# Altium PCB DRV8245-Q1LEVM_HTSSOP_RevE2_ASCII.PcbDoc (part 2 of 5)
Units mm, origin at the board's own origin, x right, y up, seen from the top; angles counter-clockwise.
Board outline 81.9 x 103.6 mm, 4 copper layers (Top Layer, Signal Layer 1, Signal Layer 2, Bottom Layer), stack 1.554 mm thick; 187 components, 116 nets, 590 pads, 1182 vias.
Unrouted connection lines stored in the file: 116.
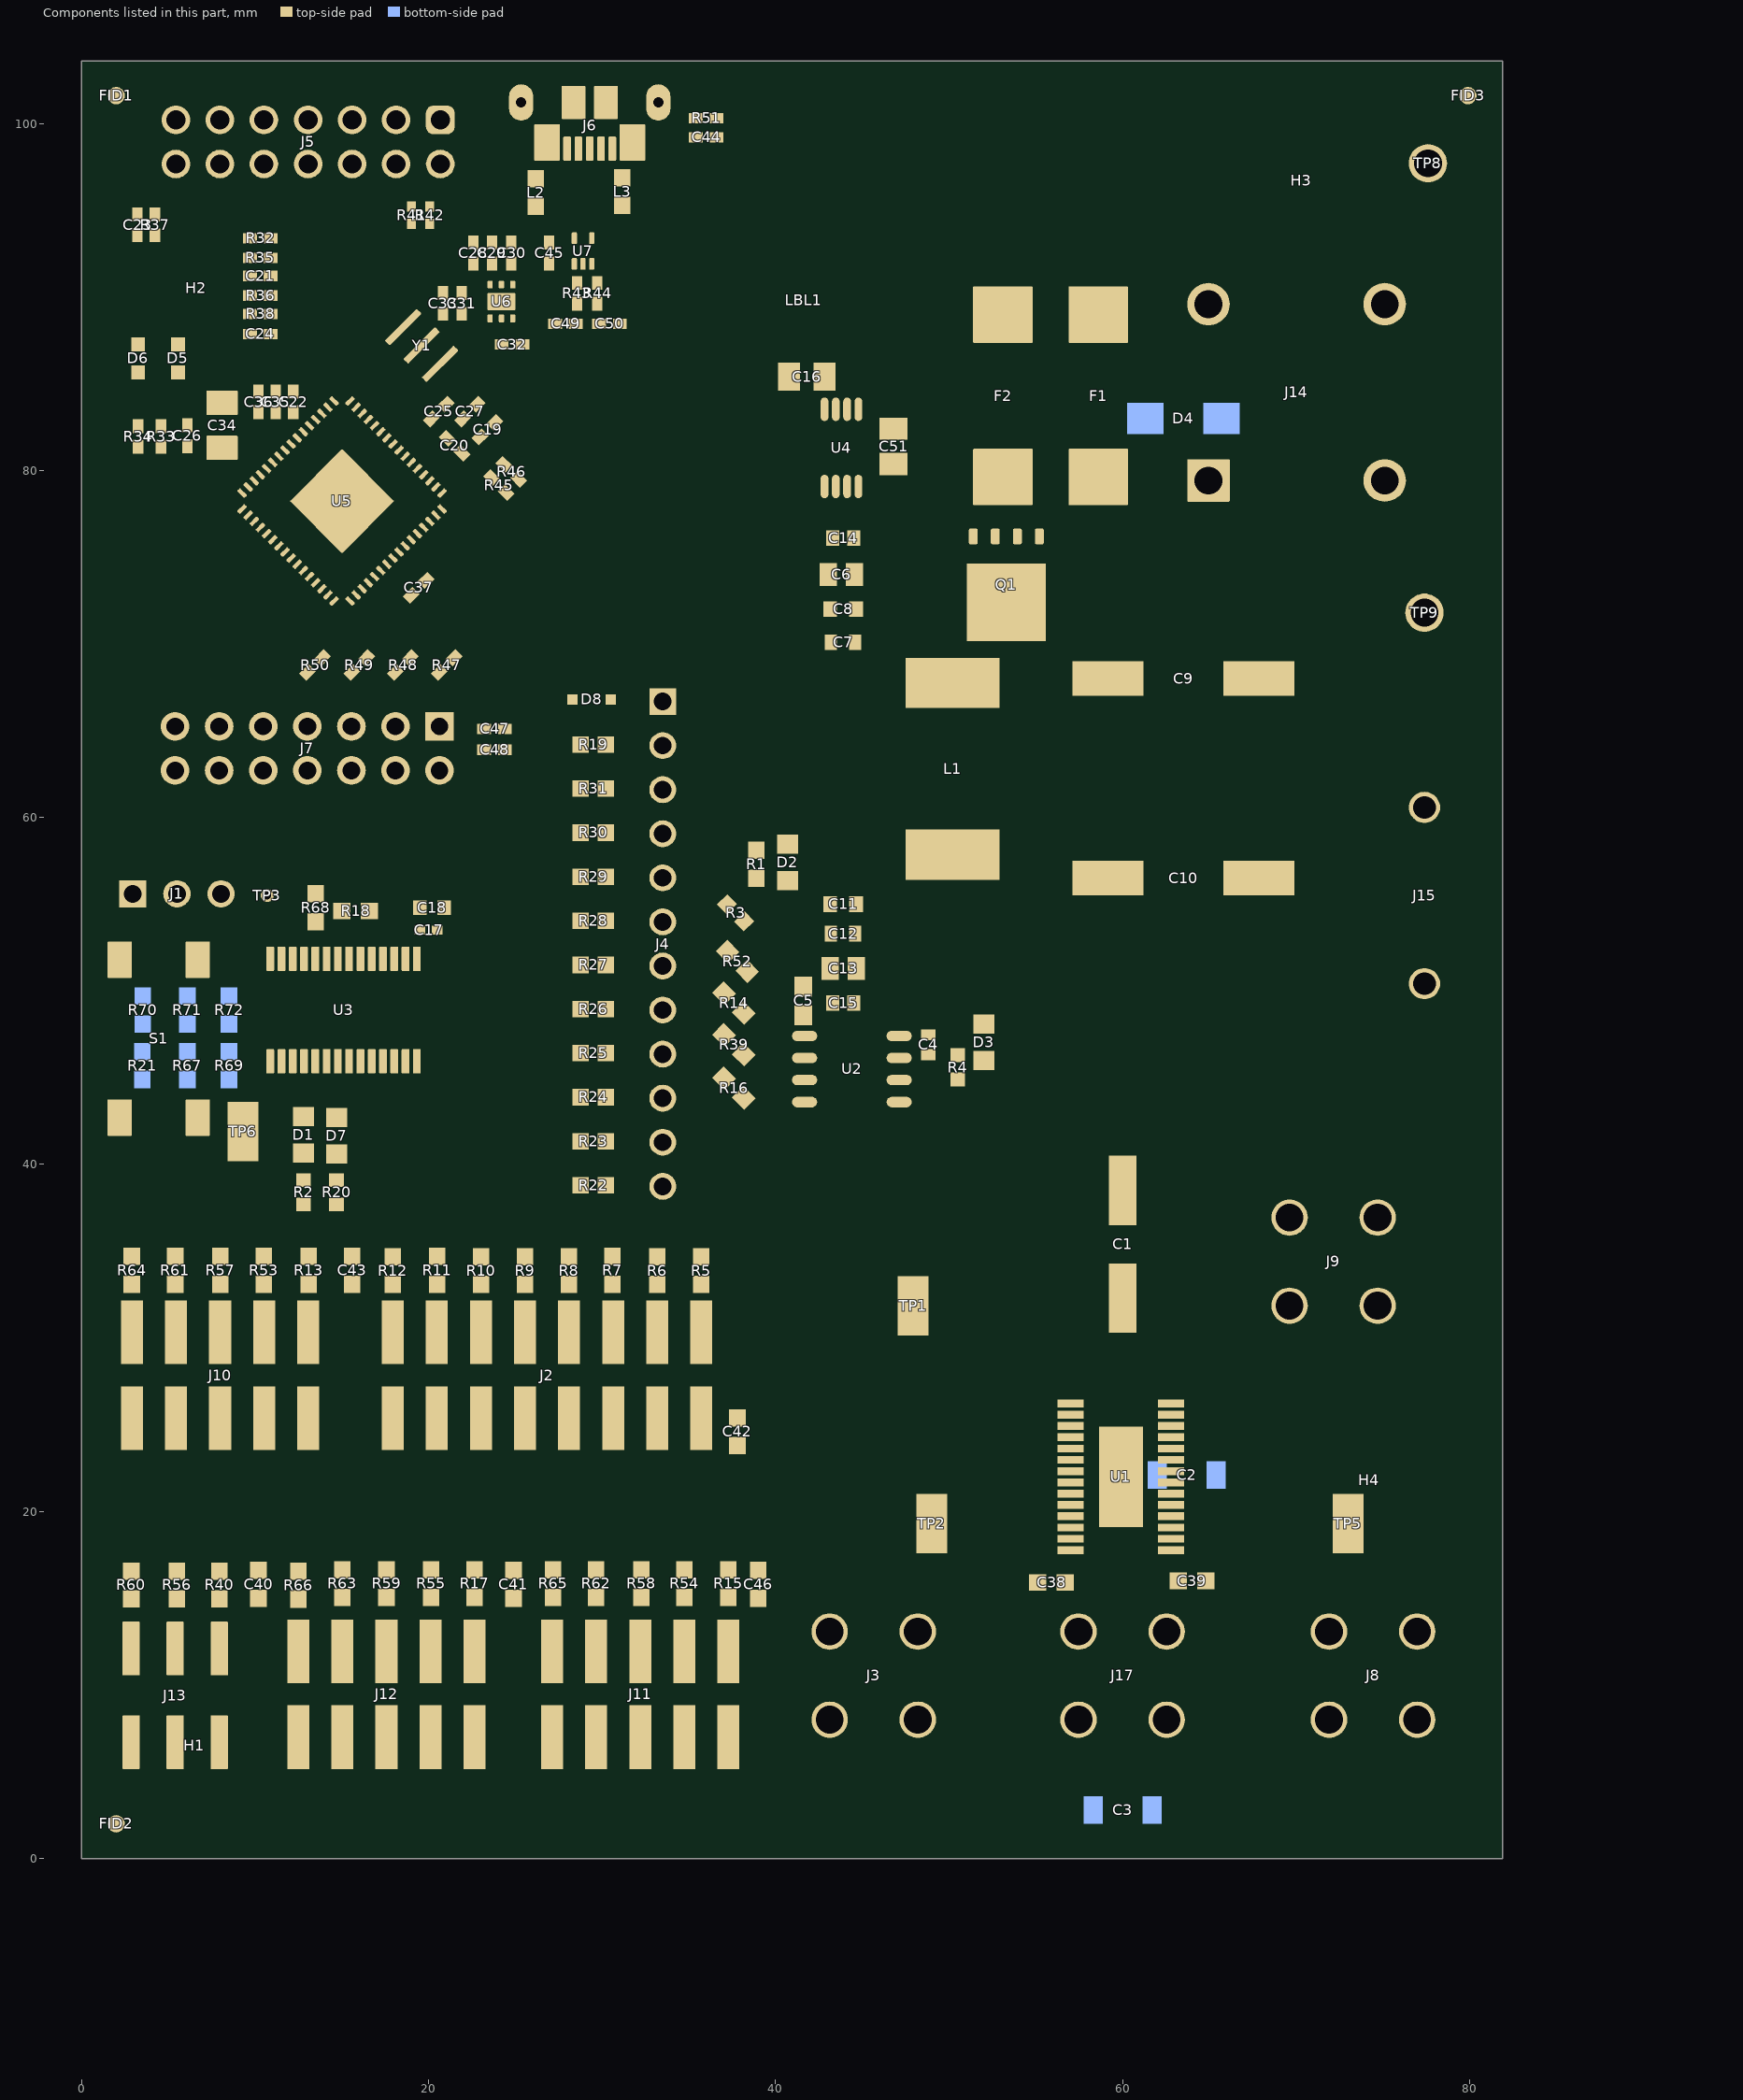
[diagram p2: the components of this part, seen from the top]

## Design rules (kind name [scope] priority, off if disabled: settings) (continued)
Clearance Clearance_6 [InNamedPolygon('BOTTOM_LAYER_EZFET_USB_SHIELD_P002') Or  InNamedPolygon('TOP_LAYER_EZFET_USB_SHIELD_P201') Or  InNamedPolygon('SIGNAL_LAYER_2_EZFET_VBUS_P018') Or  InNamedPolygon('SIGNAL_LAYER_2_EZFET_VCC_P016')] p87: gap=0.254 ignorepadtopadclearanceinfootprint=TRUE except(0: Arc-Hole Track-Hole SMDPad-Hole THPad-Hole Via-Hole Fill-Hole Poly-Hole Region-Hole Text-Hole)
Clearance Clearance_5 [InNamedPolygon('TOP_LAYER_NONET_P072')] p88: gap=0.254 ignorepadtopadclearanceinfootprint=TRUE except(0: Arc-Hole Track-Hole SMDPad-Hole THPad-Hole Via-Hole Fill-Hole Poly-Hole Region-Hole Text-Hole)
Clearance Clearance_4 [InNamedPolygon('TOP_LAYER_VM_P123') Or  InNamedPolygon('TOP_LAYER_VM_P123') Or  InNamedPolygon('TOP_LAYER_VM_P123')] p89: gap=0.254 ignorepadtopadclearanceinfootprint=TRUE except(0: Arc-Hole Track-Hole SMDPad-Hole THPad-Hole Via-Hole Fill-Hole Poly-Hole Region-Hole Text-Hole)
Clearance Clearance_3 [InNamedPolygon('TOP_LAYER_VM_P042') Or  InNamedPolygon('TOP_LAYER_VM_P044') Or  InNamedPolygon('TOP_LAYER_OUT2_P040') Or  InNamedPolygon('TOP_LAYER_OUT1_P038')] p90: gap=0.254 ignorepadtopadclearanceinfootprint=TRUE except(0: Arc-Hole Track-Hole SMDPad-Hole THPad-Hole Via-Hole Fill-Hole Poly-Hole Region-Hole Text-Hole)
Clearance Clearance_2 [InNamedPolygon('TOP_LAYER_OUT2_P040')] p91: gap=0.254 ignorepadtopadclearanceinfootprint=TRUE except(0: Arc-Hole Track-Hole SMDPad-Hole THPad-Hole Via-Hole Fill-Hole Poly-Hole Region-Hole Text-Hole)
Clearance Clearance_1 [InNamedPolygon('TOP_LAYER_VM_P046')] p92: gap=0.152 ignorepadtopadclearanceinfootprint=TRUE except(0: Arc-Hole Track-Hole SMDPad-Hole THPad-Hole Via-Hole Fill-Hole Poly-Hole Region-Hole Text-Hole)
Clearance Clearance_Keepouts [((IsTrack Or IsArc) And Not InPoly) And IsFree and IsKeepOut vs ((IsTrack Or IsArc) And Not InPoly) And IsFree and IsKeepOut] p93: gap=0 ignorepadtopadclearanceinfootprint=FALSE
Clearance Clearance_Poly [InPolygon] p94: gap=0.635 ignorepadtopadclearanceinfootprint=TRUE
Clearance Clearance_FiducialMark [IsKeepOut and InComponentClass('FiducialMark') vs IsPad and InComponentClass('FiducialMark')] p95: gap=0 ignorepadtopadclearanceinfootprint=FALSE
Clearance [All] p96: gap=0.2 ignorepadtopadclearanceinfootprint=TRUE
ComponentClearance [All] p0: scope1count=1 scope1_0_kind=Board scope1_0_value=Board scope2count=1 scope2_0_kind=Board scope2_0_value=Board commentlength=0 gap=0.762 collisioncheckmode=3
ComponentClearance ComponentClearance_THtoTH [All] p0 off: scope1count=1 scope1_0_kind=Board scope1_0_value=Board scope2count=1 scope2_0_kind=Board scope2_0_value=Board commentlength=54 gap=0.762 collisioncheckmode=3 // Protel DXP Scope 2 Expression Was: IsThruComponent
ComponentClearance ComponentClearance_THtoSMT [All] p0 off: scope1count=1 scope1_0_kind=Board scope1_0_value=Board scope2count=1 scope2_0_kind=Board scope2_0_value=Board commentlength=53 gap=1.016 collisioncheckmode=3 // Protel DXP Scope 2 Expression Was: IsSMTComponent
ComponentClearance ComponentClearance_SmallPassives [All] p0 off: scope1count=1 scope1_0_kind=Board scope1_0_value=Board scope2count=1 scope2_0_kind=Board scope2_0_value=Board commentlength=508 gap=0.38 collisioncheckmode=3 // Protel DXP Scope 2 Expression Was: HasFootprint('0201*') or HasFootprint('0402*') or HasFootprint('0508') or HasFootprint('0603*') or HasFootprint('0612') or HasFootprint('0805*') or HasFootprint('0815*') or HasFootprint('0830*') or HasFootprint('1206*') or HasFootprint('1210*') or HasFootprint('1808*') or HasFootprint('1812*') or HasFootprint('1825*') or HasFootprint('2010*') or HasFootprint('2220*') or HasFootprint('2225*') or HasFootprint('2512*') or HasFootprint('2728*') or HasFootprint('3518*')
ComponentClearance ComponentClearance_MountingHoles [All] p0: scope1count=1 scope1_0_kind=ComponentClass scope1_0_value="Mounting Holes" scope2count=1 scope2_0_kind=Board scope2_0_value=Board commentlength=0 gap=6.35 collisioncheckmode=3
ComponentClearance ComponentClearance_ScrewToNut [All] p0 off: scope1count=1 scope1_0_kind=Board scope1_0_value=Board scope2count=1 scope2_0_kind=Board scope2_0_value=Board commentlength=71 gap=0.127 collisioncheckmode=3 // Protel DXP Scope 2 Expression Was: (HasFootprint('Keystone_1902C'))
ComponentClearance ComponentClearance_Logo [All] p0: scope1count=1 scope1_0_kind=ComponentClass scope1_0_value=Logo scope2count=1 scope2_0_kind=Board scope2_0_value=Board commentlength=0 gap=1.27 collisioncheckmode=3
ComponentClearance ComponentClearance_Shunt [All] p0: scope1count=1 scope1_0_kind=ComponentClass scope1_0_value=Header scope2count=1 scope2_0_kind=ComponentClass scope2_0_value=Shunt commentlength=0 gap=0 collisioncheckmode=3
ComponentClearance ComponentClearance_MountingHoles_FiducialMarks [All] p0: scope1count=1 scope1_0_kind=ComponentClass scope1_0_value="Mounting Holes" scope2count=1 scope2_0_kind=ComponentClass scope2_0_value=FiducialMark commentlength=0 gap=1.27 collisioncheckmode=3
ComponentClearance ComponentClearance_MountingHoles_FiducialMarks [InComponentClass('Mounting Holes') vs InComponentClass('FiducialMark')] p1: gap=1.27 collisioncheckmode=3 verticalgap=0.254 showdistances=FALSE
ComponentClearance ComponentClearance_Shunt [InComponentClass('Header') vs InComponentClass('Shunt')] p2: gap=0 collisioncheckmode=3 verticalgap=0 showdistances=FALSE
ComponentClearance ComponentClearance_Logo [InComponentClass('Logo')] p3: gap=1.27 collisioncheckmode=3 verticalgap=0.254 showdistances=FALSE
ComponentClearance ComponentClearance_ScrewToNut [(HasFootprint('NY PMS 440 0025 PH')) vs (HasFootprint('Keystone_1902C'))] p4: gap=0.127 collisioncheckmode=3 verticalgap=0.254 showdistances=FALSE
ComponentClearance ComponentClearance_MountingHoles [InComponentClass('Mounting Holes')] p5: gap=6.35 collisioncheckmode=3 verticalgap=2540 showdistances=FALSE
ComponentClearance ComponentClearance_SmallPassives [HasFootprint('0201*') or HasFootprint('0402*') or HasFootprint('0508') or HasFootprint('0603*') or HasFootprint('0612') or HasFootprint('0805*') or HasFootprint('0815*') or HasFootprint('0830*') or HasFootprint('1206*') or HasFootprint('1210*') or HasFootprint('1808*') or HasFootprint('1812*') or HasFootprint('1825*') or HasFootprint('2010*') or HasFootprint('2220*') or HasFootprint('2225*') or HasFootprint('2512*') or HasFootprint('2728*') or HasFootprint('3518*') vs HasFootprint('0201*') or HasFootprint('0402*') or HasFootprint('0508') or HasFootprint('0603*') or HasFootprint('0612') or HasFootprint('0805*') or HasFootprint('0815*') or HasFootprint('0830*') or HasFootprint('1206*') or HasFootprint('1210*') or HasFootprint('1808*') or HasFootprint('1812*') or HasFootprint('1825*') or HasFootprint('2010*') or HasFootprint('2220*') or HasFootprint('2225*') or HasFootprint('2512*') or HasFootprint('2728*') or HasFootprint('3518*')] p6: gap=0.38 collisioncheckmode=3 verticalgap=0.254 showdistances=FALSE
ComponentClearance ComponentClearance_THtoSMT [IsThruComponent vs IsSMTComponent] p7: gap=1.016 collisioncheckmode=3 verticalgap=0.762 showdistances=FALSE
ComponentClearance ComponentClearance_THtoTH [IsThruComponent vs IsThruComponent] p8: gap=0.762 collisioncheckmode=3 verticalgap=0.762 showdistances=FALSE
ComponentClearance [All] p9: gap=0.762 collisioncheckmode=3 verticalgap=0.254 showdistances=FALSE
DiffPairsRouting [All] p0: scope1count=1 scope1_0_kind=Board scope1_0_value=Board scope2count=1 scope2_0_kind=Board scope2_0_value=Board commentlength=0
DiffPairsRouting [All] p1: maxlimit=2.54 minlimit=0.254 mostfreqgap=0.254 toplayer_minwidth=0.16 toplayer_maxwidth=0.381 toplayer_prefwidth=0.254 midlayer1_minwidth=0.381 midlayer1_maxwidth=0.381 midlayer1_prefwidth=0.381 midlayer2_minwidth=0.381 midlayer2_maxwidth=0.381 midlayer2_prefwidth=0.381 bottomlayer_minwidth=0.16 bottomlayer_maxwidth=0.381 bottomlayer_prefwidth=0.254 maxuncoupledlength=25.4
FabricationTestPointUsage TestPointUsage [All] p0: scope1count=1 scope1_0_kind=Board scope1_0_value=Board scope2count=1 scope2_0_kind=Board scope2_0_value=Board commentlength=0 valid=2 allowmultiple=FALSE
FabricationTestPointUsage TestPointUsage [All] p1: valid=2 allowmultiple=FALSE
FabricationTestpoint Testpoint [All] p0: scope1count=1 scope1_0_kind=Board scope1_0_value=Board scope2count=1 scope2_0_kind=Board scope2_0_value=Board commentlength=0 side=3 testpointundercomponent=TRUE minsize=1.016 maxsize=2.54 preferedsize=1.524 minholesize=0 maxholesize=1.016 preferedholesize=0.813 testpointgrid=0.025
FabricationTestpoint Testpoint [All] p1: side=3 testpointundercomponent=TRUE minsize=1.016 maxsize=2.54 preferedsize=1.524 minholesize=0 maxholesize=1.016 preferedholesize=0.813 testpointgrid=0.025 allowsidetop=TRUE allowsidebottom=TRUE usegrid=TRUE gridtolerance=0
FanoutControl Fanout_Small [All] p0 off: scope1count=1 scope1_0_kind=Board scope1_0_value=Board scope2count=1 scope2_0_kind=Board scope2_0_value=Board commentlength=84 // Protel DXP Scope 1 Expression Was: (CompPinCount < 5)   Fanout_Small (Default Rule)
FanoutControl Fanout_Default [All] p0: scope1count=1 scope1_0_kind=Board scope1_0_value=Board scope2count=1 scope2_0_kind=Board scope2_0_value=Board commentlength=30 // Fanout_Default (Default Rule)
FanoutControl Fanout_SOIC [All] p0 off: scope1count=1 scope1_0_kind=Board scope1_0_value=Board scope2count=1 scope2_0_kind=Board scope2_0_value=Board commentlength=71 // Protel DXP Scope 1 Expression Was: IsSOIC   Fanout_SOIC (Default Rule)
FanoutControl Fanout_BGA [All] p0 off: scope1count=1 scope1_0_kind=Board scope1_0_value=Board scope2count=1 scope2_0_kind=Board scope2_0_value=Board commentlength=69 // Protel DXP Scope 1 Expression Was: IsBGA   Fanout_BGA (Default Rule)
FanoutControl Fanout_LCC [All] p0 off: scope1count=1 scope1_0_kind=Board scope1_0_value=Board scope2count=1 scope2_0_kind=Board scope2_0_value=Board commentlength=69 // Protel DXP Scope 1 Expression Was: IsLCC   Fanout_LCC (Default Rule)
FanoutControl Fanout_LCC [IsLCC] p1: bgadir=Out bgaviamode=Centered fanoutstyle=Auto fanoutdirection=Alternating viagrid=0.025 // Fanout_LCC (Default Rule)
FanoutControl Fanout_BGA [IsBGA] p2: bgadir=Out bgaviamode=Centered fanoutstyle=Auto fanoutdirection=Alternating viagrid=0.025 // Fanout_BGA (Default Rule)
FanoutControl Fanout_Default [All] p4: bgadir=Out bgaviamode=Centered fanoutstyle=Auto fanoutdirection=Alternating viagrid=0.025 // Fanout_Default (Default Rule)
FanoutControl Fanout_Small [(CompPinCount < 5)] p5: bgadir=Out bgaviamode=Centered fanoutstyle=Auto fanoutdirection=OutThenIn viagrid=0.025 // Fanout_Small (Default Rule)
Height [All] p0: scope1count=1 scope1_0_kind=Board scope1_0_value=Board scope2count=1 scope2_0_kind=Board scope2_0_value=Board commentlength=0
HoleSize [All] p0: scope1count=1 scope1_0_kind=Board scope1_0_value=Board scope2count=1 scope2_0_kind=Board scope2_0_value=Board commentlength=0 absolutevalues=TRUE maxlimit=6.375 minlimit=0.2 maxpercent=80.000 minpercent=20.000
HoleSize [All] p1: absolutevalues=TRUE maxlimit=6.375 minlimit=0.2 maxpercent=80.000 minpercent=20.000
HoleToHoleClearance [All] p0: scope1count=1 scope1_0_kind=Board scope1_0_value=Board scope2count=1 scope2_0_kind=Board scope2_0_value=Board commentlength=0
LayerPairs [All] p0: scope1count=1 scope1_0_kind=Board scope1_0_value=Board scope2count=1 scope2_0_kind=Board scope2_0_value=Board commentlength=0 enforce=TRUE
MinimumAnnularRing [All] p0: scope1count=1 scope1_0_kind=Board scope1_0_value=Board scope2count=1 scope2_0_kind=Board scope2_0_value=Board commentlength=0 minimumring=0.2
MinimumAnnularRing MinimumAnnularRing_ThermalPadVias [All] p0 off: scope1count=1 scope1_0_kind=Board scope1_0_value=Board scope2count=1 scope2_0_kind=Board scope2_0_value=Board commentlength=63 minimumring=0.15 // Protel DXP Scope 1 Expression Was: IsVia and InAnyComponent
MinimumAnnularRing MinimumAnnularRing_ThermalPadVias [IsVia and InAnyComponent] p1: minimumring=0.15
MinimumAnnularRing [All] p2: minimumring=0.2
MinimumSolderMaskSliver [All] p0: scope1count=1 scope1_0_kind=Board scope1_0_value=Board scope2count=1 scope2_0_kind=Board scope2_0_value=Board commentlength=0
MinimumSolderMaskSliver MinimumSolderMaskSliver_Logo [All] p0: scope1count=1 scope1_0_kind=ComponentClass scope1_0_value=Logo scope2count=1 scope2_0_kind=ComponentClass scope2_0_value=Logo commentlength=0
MinimumSolderMaskSliver MinimumSolderMaskSliver_Logo [InComponentClass('Logo') vs InComponentClass('Logo')] p1: minsoldermaskwidth=0.018
MinimumSolderMaskSliver [All] p2: minsoldermaskwidth=0.1
NetAntennae [All] p0: scope1count=1 scope1_0_kind=Board scope1_0_value=Board scope2count=1 scope2_0_kind=Board scope2_0_value=Board commentlength=0
PasteMaskExpansion [All] p0: scope1count=1 scope1_0_kind=Board scope1_0_value=Board scope2count=1 scope2_0_kind=Board scope2_0_value=Board commentlength=0 expansion=0
PlaneClearance [All] p0: scope1count=1 scope1_0_kind=Board scope1_0_value=Board scope2count=1 scope2_0_kind=Board scope2_0_value=Board commentlength=0 clearance=0.508
PlaneConnect [All] p0: scope1count=1 scope1_0_kind=Board scope1_0_value=Board scope2count=1 scope2_0_kind=Board scope2_0_value=Board commentlength=0 planeconnectstyle=Relief reliefexpansion=0.254 reliefentries=4 reliefconductorwidth=0.254 reliefairgap=0.254
PlaneConnect [All] p1: planeconnectstyle=Relief reliefexpansion=0.254 reliefentries=4 reliefconductorwidth=0.254 reliefairgap=0.254
PolygonConnect PolygonConnect_87 [All] p0 off: scope1count=1 scope1_0_kind=Board scope1_0_value=Board scope2count=1 scope2_0_kind=Board scope2_0_value=Board commentlength=74 connectstyle=Direct reliefconductorwidth=0.254 reliefentries=4 polygonreliefangle="90 Angle" // Protel DXP Scope 2 Expression Was: IsNamedPolygon('TOP_LAYER_VM_P125')
PolygonConnect PolygonConnect_86 [All] p0 off: scope1count=1 scope1_0_kind=Board scope1_0_value=Board scope2count=1 scope2_0_kind=Board scope2_0_value=Board commentlength=78 connectstyle=Direct reliefconductorwidth=0.254 reliefentries=4 polygonreliefangle="90 Angle" // Protel DXP Scope 2 Expression Was: IsNamedPolygon('TOP_LAYER_NONET_P-001')
PolygonConnect PolygonConnect_85 [All] p0 off: scope1count=1 scope1_0_kind=Board scope1_0_value=Board scope2count=1 scope2_0_kind=Board scope2_0_value=Board commentlength=79 connectstyle=Direct reliefconductorwidth=0.254 reliefentries=4 polygonreliefangle="90 Angle" // Protel DXP Scope 2 Expression Was: IsNamedPolygon('BOTTOM_LAYER_OUT2_P211')
PolygonConnect PolygonConnect_84 [All] p0 off: scope1count=1 scope1_0_kind=Board scope1_0_value=Board scope2count=1 scope2_0_kind=Board scope2_0_value=Board commentlength=79 connectstyle=Direct reliefconductorwidth=0.254 reliefentries=4 polygonreliefangle="90 Angle" // Protel DXP Scope 2 Expression Was: IsNamedPolygon('BOTTOM_LAYER_OUT1_P205')
PolygonConnect PolygonConnect_83 [All] p0 off: scope1count=1 scope1_0_kind=Board scope1_0_value=Board scope2count=1 scope2_0_kind=Board scope2_0_value=Board commentlength=79 connectstyle=Direct reliefconductorwidth=0.254 reliefentries=4 polygonreliefangle="90 Angle" // Protel DXP Scope 2 Expression Was: IsNamedPolygon('BOTTOM_LAYER_OUT1_P205')
PolygonConnect PolygonConnect_82 [All] p0 off: scope1count=1 scope1_0_kind=Board scope1_0_value=Board scope2count=1 scope2_0_kind=Board scope2_0_value=Board commentlength=78 connectstyle=Direct reliefconductorwidth=0.254 reliefentries=4 polygonreliefangle="90 Angle" // Protel DXP Scope 2 Expression Was: IsNamedPolygon('BOTTOM_LAYER_GND_P204')
PolygonConnect PolygonConnect_81 [All] p0 off: scope1count=1 scope1_0_kind=Board scope1_0_value=Board scope2count=1 scope2_0_kind=Board scope2_0_value=Board commentlength=75 connectstyle=Direct reliefconductorwidth=0.254 reliefentries=4 polygonreliefangle="90 Angle" // Protel DXP Scope 2 Expression Was: IsNamedPolygon('TOP_LAYER_GND_P237')
PolygonConnect PolygonConnect_80 [All] p0 off: scope1count=1 scope1_0_kind=Board scope1_0_value=Board scope2count=1 scope2_0_kind=Board scope2_0_value=Board commentlength=75 connectstyle=Direct reliefconductorwidth=0.254 reliefentries=4 polygonreliefangle="90 Angle" // Protel DXP Scope 2 Expression Was: IsNamedPolygon('TOP_LAYER_GND_P086')
PolygonConnect PolygonConnect_79 [All] p0 off: scope1count=1 scope1_0_kind=Board scope1_0_value=Board scope2count=1 scope2_0_kind=Board scope2_0_value=Board commentlength=74 connectstyle=Direct reliefconductorwidth=0.254 reliefentries=4 polygonreliefangle="90 Angle" // Protel DXP Scope 2 Expression Was: IsNamedPolygon('TOP_LAYER_VM_P229')
PolygonConnect PolygonConnect_78 [All] p0 off: scope1count=1 scope1_0_kind=Board scope1_0_value=Board scope2count=1 scope2_0_kind=Board scope2_0_value=Board commentlength=75 connectstyle=Direct reliefconductorwidth=0.254 reliefentries=4 polygonreliefangle="90 Angle" // Protel DXP Scope 2 Expression Was: IsNamedPolygon('TOP_LAYER_GND_P086')
PolygonConnect PolygonConnect_77 [All] p0 off: scope1count=1 scope1_0_kind=Board scope1_0_value=Board scope2count=1 scope2_0_kind=Board scope2_0_value=Board commentlength=76 connectstyle=Direct reliefconductorwidth=0.254 reliefentries=4 polygonreliefangle="90 Angle" // Protel DXP Scope 2 Expression Was: IsNamedPolygon('TOP_LAYER_OUT1_P221')
PolygonConnect PolygonConnect_76 [All] p0 off: scope1count=1 scope1_0_kind=Board scope1_0_value=Board scope2count=1 scope2_0_kind=Board scope2_0_value=Board commentlength=76 connectstyle=Direct reliefconductorwidth=0.254 reliefentries=4 polygonreliefangle="90 Angle" // Protel DXP Scope 2 Expression Was: IsNamedPolygon('TOP_LAYER_OUT2_P173')
PolygonConnect PolygonConnect_75 [All] p0 off: scope1count=1 scope1_0_kind=Board scope1_0_value=Board scope2count=1 scope2_0_kind=Board scope2_0_value=Board commentlength=76 connectstyle=Direct reliefconductorwidth=0.254 reliefentries=4 polygonreliefangle="90 Angle" // Protel DXP Scope 2 Expression Was: IsNamedPolygon('TOP_LAYER_OUT2_P173')
PolygonConnect PolygonConnect_74 [All] p0 off: scope1count=1 scope1_0_kind=Board scope1_0_value=Board scope2count=1 scope2_0_kind=Board scope2_0_value=Board commentlength=76 connectstyle=Direct reliefconductorwidth=0.254 reliefentries=4 polygonreliefangle="90 Angle" // Protel DXP Scope 2 Expression Was: IsNamedPolygon('TOP_LAYER_OUT2_P173')
PolygonConnect PolygonConnect_73 [All] p0 off: scope1count=1 scope1_0_kind=Board scope1_0_value=Board scope2count=1 scope2_0_kind=Board scope2_0_value=Board commentlength=76 connectstyle=Direct reliefconductorwidth=0.254 reliefentries=4 polygonreliefangle="90 Angle" // Protel DXP Scope 2 Expression Was: IsNamedPolygon('TOP_LAYER_OUT1_P221')
PolygonConnect PolygonConnect_72 [All] p0 off: scope1count=1 scope1_0_kind=Board scope1_0_value=Board scope2count=1 scope2_0_kind=Board scope2_0_value=Board commentlength=75 connectstyle=Direct reliefconductorwidth=0.254 reliefentries=4 polygonreliefangle="90 Angle" // Protel DXP Scope 2 Expression Was: IsNamedPolygon('TOP_LAYER_GND_P121')
PolygonConnect PolygonConnect_71 [All] p0 off: scope1count=1 scope1_0_kind=Board scope1_0_value=Board scope2count=1 scope2_0_kind=Board scope2_0_value=Board commentlength=118 connectstyle=Direct reliefconductorwidth=0.254 reliefentries=4 polygonreliefangle="90 Angle" // Protel DXP Scope 2 Expression Was: IsNamedPolygon('TOP_LAYER_OUT2_P173') Or  IsNamedPolygon('TOP_LAYER_OUT1_P129')
PolygonConnect PolygonConnect_70 [All] p0 off: scope1count=1 scope1_0_kind=Board scope1_0_value=Board scope2count=1 scope2_0_kind=Board scope2_0_value=Board commentlength=76 connectstyle=Direct reliefconductorwidth=0.254 reliefentries=4 polygonreliefangle="90 Angle" // Protel DXP Scope 2 Expression Was: IsNamedPolygon('TOP_LAYER_OUT2_P173')
PolygonConnect PolygonConnect_69 [All] p0 off: scope1count=1 scope1_0_kind=Board scope1_0_value=Board scope2count=1 scope2_0_kind=Board scope2_0_value=Board commentlength=76 connectstyle=Direct reliefconductorwidth=0.254 reliefentries=4 polygonreliefangle="90 Angle" // Protel DXP Scope 2 Expression Was: IsNamedPolygon('TOP_LAYER_OUT1_P129')
PolygonConnect PolygonConnect_68 [All] p0 off: scope1count=1 scope1_0_kind=Board scope1_0_value=Board scope2count=1 scope2_0_kind=Board scope2_0_value=Board commentlength=74 connectstyle=Direct reliefconductorwidth=0.254 reliefentries=4 polygonreliefangle="90 Angle" // Protel DXP Scope 2 Expression Was: IsNamedPolygon('TOP_LAYER_VM_P085')
PolygonConnect PolygonConnect_67 [All] p0 off: scope1count=1 scope1_0_kind=Board scope1_0_value=Board scope2count=1 scope2_0_kind=Board scope2_0_value=Board commentlength=79 connectstyle=Direct reliefconductorwidth=0.254 reliefentries=4 polygonreliefangle="90 Angle" // Protel DXP Scope 2 Expression Was: IsNamedPolygon('BOTTOM_LAYER_P_IN_P174')
PolygonConnect PolygonConnect_66 [All] p0 off: scope1count=1 scope1_0_kind=Board scope1_0_value=Board scope2count=1 scope2_0_kind=Board scope2_0_value=Board commentlength=82 connectstyle=Direct reliefconductorwidth=0.254 reliefentries=4 polygonreliefangle="90 Angle" // Protel DXP Scope 2 Expression Was: IsNamedPolygon('BOTTOM_LAYER_NETF1_2_P203')
PolygonConnect PolygonConnect_65 [All] p0 off: scope1count=1 scope1_0_kind=Board scope1_0_value=Board scope2count=1 scope2_0_kind=Board scope2_0_value=Board commentlength=79 connectstyle=Direct reliefconductorwidth=0.254 reliefentries=4 polygonreliefangle="90 Angle" // Protel DXP Scope 2 Expression Was: IsNamedPolygon('BOTTOM_LAYER_VBAT_P165')
PolygonConnect PolygonConnect_64 [All] p0 off: scope1count=1 scope1_0_kind=Board scope1_0_value=Board scope2count=1 scope2_0_kind=Board scope2_0_value=Board commentlength=74 connectstyle=Direct reliefconductorwidth=0.254 reliefentries=4 polygonreliefangle="90 Angle" // Protel DXP Scope 2 Expression Was: IsNamedPolygon('TOP_LAYER_VM_P167')
PolygonConnect PolygonConnect_63 [All] p0 off: scope1count=1 scope1_0_kind=Board scope1_0_value=Board scope2count=1 scope2_0_kind=Board scope2_0_value=Board commentlength=74 connectstyle=Direct reliefconductorwidth=0.254 reliefentries=4 polygonreliefangle="90 Angle" // Protel DXP Scope 2 Expression Was: IsNamedPolygon('TOP_LAYER_VM_P167')
PolygonConnect PolygonConnect_62 [All] p0 off: scope1count=1 scope1_0_kind=Board scope1_0_value=Board scope2count=1 scope2_0_kind=Board scope2_0_value=Board commentlength=74 connectstyle=Direct reliefconductorwidth=0.254 reliefentries=4 polygonreliefangle="90 Angle" // Protel DXP Scope 2 Expression Was: IsNamedPolygon('TOP_LAYER_VM_P171')
PolygonConnect PolygonConnect_61 [All] p0 off: scope1count=1 scope1_0_kind=Board scope1_0_value=Board scope2count=1 scope2_0_kind=Board scope2_0_value=Board commentlength=80 connectstyle=Direct reliefconductorwidth=0.254 reliefentries=4 polygonreliefangle="90 Angle" // Protel DXP Scope 2 Expression Was: IsNamedPolygon('SIGNAL_LAYER_2_GND_P199')
PolygonConnect PolygonConnect_60 [All] p0 off: scope1count=1 scope1_0_kind=Board scope1_0_value=Board scope2count=1 scope2_0_kind=Board scope2_0_value=Board commentlength=84 connectstyle=Direct reliefconductorwidth=0.254 reliefentries=4 polygonreliefangle="90 Angle" // Protel DXP Scope 2 Expression Was: IsNamedPolygon('SIGNAL_LAYER_2_NETF1_2_P196')
PolygonConnect PolygonConnect_59 [All] p0 off: scope1count=1 scope1_0_kind=Board scope1_0_value=Board scope2count=1 scope2_0_kind=Board scope2_0_value=Board commentlength=81 connectstyle=Direct reliefconductorwidth=0.254 reliefentries=4 polygonreliefangle="90 Angle" // Protel DXP Scope 2 Expression Was: IsNamedPolygon('SIGNAL_LAYER_2_VBAT_P197')
PolygonConnect PolygonConnect_58 [All] p0 off: scope1count=1 scope1_0_kind=Board scope1_0_value=Board scope2count=1 scope2_0_kind=Board scope2_0_value=Board commentlength=81 connectstyle=Direct reliefconductorwidth=0.254 reliefentries=4 polygonreliefangle="90 Angle" // Protel DXP Scope 2 Expression Was: IsNamedPolygon('SIGNAL_LAYER_2_P_IN_P198')
PolygonConnect PolygonConnect_57 [All] p0 off: scope1count=1 scope1_0_kind=Board scope1_0_value=Board scope2count=1 scope2_0_kind=Board scope2_0_value=Board commentlength=80 connectstyle=Direct reliefconductorwidth=0.254 reliefentries=4 polygonreliefangle="90 Angle" // Protel DXP Scope 2 Expression Was: IsNamedPolygon('SIGNAL_LAYER_2_3V3_P194')
PolygonConnect PolygonConnect_56 [All] p0 off: scope1count=1 scope1_0_kind=Board scope1_0_value=Board scope2count=1 scope2_0_kind=Board scope2_0_value=Board commentlength=79 connectstyle=Direct reliefconductorwidth=0.254 reliefentries=4 polygonreliefangle="90 Angle" // Protel DXP Scope 2 Expression Was: IsNamedPolygon('TOP_LAYER_NETF1_2_P207')
PolygonConnect PolygonConnect_55 [All] p0 off: scope1count=1 scope1_0_kind=Board scope1_0_value=Board scope2count=1 scope2_0_kind=Board scope2_0_value=Board commentlength=76 connectstyle=Direct reliefconductorwidth=0.254 reliefentries=4 polygonreliefangle="90 Angle" // Protel DXP Scope 2 Expression Was: IsNamedPolygon('TOP_LAYER_VBAT_P223')
PolygonConnect PolygonConnect_54 [All] p0 off: scope1count=1 scope1_0_kind=Board scope1_0_value=Board scope2count=1 scope2_0_kind=Board scope2_0_value=Board commentlength=76 connectstyle=Direct reliefconductorwidth=0.254 reliefentries=4 polygonreliefangle="90 Angle" // Protel DXP Scope 2 Expression Was: IsNamedPolygon('TOP_LAYER_P_IN_P227')
PolygonConnect PolygonConnect_53 [All] p0 off: scope1count=1 scope1_0_kind=Board scope1_0_value=Board scope2count=1 scope2_0_kind=Board scope2_0_value=Board commentlength=75 connectstyle=Direct reliefconductorwidth=0.254 reliefentries=4 polygonreliefangle="90 Angle" // Protel DXP Scope 2 Expression Was: IsNamedPolygon('TOP_LAYER_GND_P086')
PolygonConnect PolygonConnect_52 [All] p0 off: scope1count=1 scope1_0_kind=Board scope1_0_value=Board scope2count=1 scope2_0_kind=Board scope2_0_value=Board commentlength=259 connectstyle=Direct reliefconductorwidth=0.254 reliefentries=4 polygonreliefangle="90 Angle" // Protel DXP Scope 2 Expression Was: IsNamedPolygon('SIGNAL_LAYER_2_VM_P177') Or  IsNamedPolygon('SIGNAL_LAYER_2_VM_P179') Or  IsNamedPolygon('SIGNAL_LAYER_2_VM_P160') Or  IsNamedPolygon('SIGNAL_LAYER_2_VM_P175') Or  IsNamedPolygon('SIGNAL_LAYER_2_VM_P181')
PolygonConnect PolygonConnect_51 [All] p0 off: scope1count=1 scope1_0_kind=Board scope1_0_value=Board scope2count=1 scope2_0_kind=Board scope2_0_value=Board commentlength=87 connectstyle=Direct reliefconductorwidth=0.254 reliefentries=4 polygonreliefangle="90 Angle" // Protel DXP Scope 2 Expression Was: IsNamedPolygon('SIGNAL_LAYER_2_EZFET_VBUS_P136')
PolygonConnect PolygonConnect_50 [All] p0 off: scope1count=1 scope1_0_kind=Board scope1_0_value=Board scope2count=1 scope2_0_kind=Board scope2_0_value=Board commentlength=86 connectstyle=Direct reliefconductorwidth=0.254 reliefentries=4 polygonreliefangle="90 Angle" // Protel DXP Scope 2 Expression Was: IsNamedPolygon('SIGNAL_LAYER_2_EZFET_VCC_P132')
PolygonConnect PolygonConnect_49 [All] p0 off: scope1count=1 scope1_0_kind=Board scope1_0_value=Board scope2count=1 scope2_0_kind=Board scope2_0_value=Board commentlength=84 connectstyle=Direct reliefconductorwidth=0.254 reliefentries=4 polygonreliefangle="90 Angle" // Protel DXP Scope 2 Expression Was: IsNamedPolygon('SIGNAL_LAYER_2_3V3_MCU_P192')
PolygonConnect PolygonConnect_48 [All] p0 off: scope1count=1 scope1_0_kind=Board scope1_0_value=Board scope2count=1 scope2_0_kind=Board scope2_0_value=Board commentlength=80 connectstyle=Direct reliefconductorwidth=0.254 reliefentries=4 polygonreliefangle="90 Angle" // Protel DXP Scope 2 Expression Was: IsNamedPolygon('SIGNAL_LAYER_1_GND_P190')
PolygonConnect PolygonConnect_47 [All] p0 off: scope1count=1 scope1_0_kind=Board scope1_0_value=Board scope2count=1 scope2_0_kind=Board scope2_0_value=Board commentlength=80 connectstyle=Direct reliefconductorwidth=0.254 reliefentries=4 polygonreliefangle="90 Angle" // Protel DXP Scope 2 Expression Was: IsNamedPolygon('SIGNAL_LAYER_1_GND_P184')
PolygonConnect PolygonConnect_46 [All] p0 off: scope1count=1 scope1_0_kind=Board scope1_0_value=Board scope2count=1 scope2_0_kind=Board scope2_0_value=Board commentlength=78 connectstyle=Direct reliefconductorwidth=0.254 reliefentries=4 polygonreliefangle="90 Angle" // Protel DXP Scope 2 Expression Was: IsNamedPolygon('BOTTOM_LAYER_GND_P241')
PolygonConnect PolygonConnect_45 [All] p0 off: scope1count=1 scope1_0_kind=Board scope1_0_value=Board scope2count=1 scope2_0_kind=Board scope2_0_value=Board commentlength=78 connectstyle=Direct reliefconductorwidth=0.254 reliefentries=4 polygonreliefangle="90 Angle" // Protel DXP Scope 2 Expression Was: IsNamedPolygon('BOTTOM_LAYER_GND_P241')
PolygonConnect PolygonConnect_44 [All] p0 off: scope1count=1 scope1_0_kind=Board scope1_0_value=Board scope2count=1 scope2_0_kind=Board scope2_0_value=Board commentlength=79 connectstyle=Direct reliefconductorwidth=0.254 reliefentries=4 polygonreliefangle="90 Angle" // Protel DXP Scope 2 Expression Was: IsNamedPolygon('BOTTOM_LAYER_OUT2_P163')
PolygonConnect PolygonConnect_43 [All] p0 off: scope1count=1 scope1_0_kind=Board scope1_0_value=Board scope2count=1 scope2_0_kind=Board scope2_0_value=Board commentlength=77 connectstyle=Direct reliefconductorwidth=0.254 reliefentries=4 polygonreliefangle="90 Angle" // Protel DXP Scope 2 Expression Was: IsNamedPolygon('BOTTOM_LAYER_VM_P166')
PolygonConnect PolygonConnect_42 [All] p0 off: scope1count=1 scope1_0_kind=Board scope1_0_value=Board scope2count=1 scope2_0_kind=Board scope2_0_value=Board commentlength=77 connectstyle=Direct reliefconductorwidth=0.254 reliefentries=4 polygonreliefangle="90 Angle" // Protel DXP Scope 2 Expression Was: IsNamedPolygon('BOTTOM_LAYER_VM_P235')
PolygonConnect PolygonConnect_41 [All] p0 off: scope1count=1 scope1_0_kind=Board scope1_0_value=Board scope2count=1 scope2_0_kind=Board scope2_0_value=Board commentlength=79 connectstyle=Direct reliefconductorwidth=0.254 reliefentries=4 polygonreliefangle="90 Angle" // Protel DXP Scope 2 Expression Was: IsNamedPolygon('BOTTOM_LAYER_OUT1_P164')
PolygonConnect PolygonConnect_40 [All] p0 off: scope1count=1 scope1_0_kind=Board scope1_0_value=Board scope2count=1 scope2_0_kind=Board scope2_0_value=Board commentlength=78 connectstyle=Direct reliefconductorwidth=0.254 reliefentries=4 polygonreliefangle="90 Angle" // Protel DXP Scope 2 Expression Was: IsNamedPolygon('BOTTOM_LAYER_GND_P162')
PolygonConnect PolygonConnect_39 [All] p0 off: scope1count=1 scope1_0_kind=Board scope1_0_value=Board scope2count=1 scope2_0_kind=Board scope2_0_value=Board commentlength=79 connectstyle=Direct reliefconductorwidth=0.254 reliefentries=4 polygonreliefangle="90 Angle" // Protel DXP Scope 2 Expression Was: IsNamedPolygon('SIGNAL_LAYER_2_VM_P160')
PolygonConnect PolygonConnect_38 [All] p0 off: scope1count=1 scope1_0_kind=Board scope1_0_value=Board scope2count=1 scope2_0_kind=Board scope2_0_value=Board commentlength=82 connectstyle=Direct reliefconductorwidth=0.254 reliefentries=4 polygonreliefangle="90 Angle" // Protel DXP Scope 2 Expression Was: IsNamedPolygon('SIGNAL_LAYER_2_NONET_P138')
PolygonConnect PolygonConnect_37 [All] p0 off: scope1count=1 scope1_0_kind=Board scope1_0_value=Board scope2count=1 scope2_0_kind=Board scope2_0_value=Board commentlength=79 connectstyle=Direct reliefconductorwidth=0.254 reliefentries=4 polygonreliefangle="90 Angle" // Protel DXP Scope 2 Expression Was: IsNamedPolygon('SIGNAL_LAYER_1_VM_P146')
PolygonConnect PolygonConnect_36 [All] p0 off: scope1count=1 scope1_0_kind=Board scope1_0_value=Board scope2count=1 scope2_0_kind=Board scope2_0_value=Board commentlength=80 connectstyle=Direct reliefconductorwidth=0.254 reliefentries=4 polygonreliefangle="90 Angle" // Protel DXP Scope 2 Expression Was: IsNamedPolygon('SIGNAL_LAYER_2_GND_P156')
PolygonConnect PolygonConnect_35 [All] p0 off: scope1count=1 scope1_0_kind=Board scope1_0_value=Board scope2count=1 scope2_0_kind=Board scope2_0_value=Board commentlength=91 connectstyle=Direct reliefconductorwidth=0.254 reliefentries=4 polygonreliefangle="90 Angle" // Protel DXP Scope 2 Expression Was: IsNamedPolygon('BOTTOM_LAYER_EZFET_USB_SHIELD_P219')
PolygonConnect PolygonConnect_34 [All] p0 off: scope1count=1 scope1_0_kind=Board scope1_0_value=Board scope2count=1 scope2_0_kind=Board scope2_0_value=Board commentlength=79 connectstyle=Direct reliefconductorwidth=0.254 reliefentries=4 polygonreliefangle="90 Angle" // Protel DXP Scope 2 Expression Was: IsNamedPolygon('SIGNAL_LAYER_1_VM_P144')
PolygonConnect PolygonConnect_33 [All] p0 off: scope1count=1 scope1_0_kind=Board scope1_0_value=Board scope2count=1 scope2_0_kind=Board scope2_0_value=Board commentlength=124 connectstyle=Direct reliefconductorwidth=0.254 reliefentries=4 polygonreliefangle="90 Angle" // Protel DXP Scope 2 Expression Was: IsNamedPolygon('SIGNAL_LAYER_1_VM_P148') Or  IsNamedPolygon('SIGNAL_LAYER_1_VM_P148')
PolygonConnect PolygonConnect_32 [All] p0 off: scope1count=1 scope1_0_kind=Board scope1_0_value=Board scope2count=1 scope2_0_kind=Board scope2_0_value=Board commentlength=80 connectstyle=Direct reliefconductorwidth=0.254 reliefentries=4 polygonreliefangle="90 Angle" // Protel DXP Scope 2 Expression Was: IsNamedPolygon('SIGNAL_LAYER_1_GND_P154')
PolygonConnect PolygonConnect_31 [All] p0 off: scope1count=1 scope1_0_kind=Board scope1_0_value=Board scope2count=1 scope2_0_kind=Board scope2_0_value=Board commentlength=82 connectstyle=Direct reliefconductorwidth=0.254 reliefentries=4 polygonreliefangle="90 Angle" // Protel DXP Scope 2 Expression Was: IsNamedPolygon('SIGNAL_LAYER_2_NONET_P138')
PolygonConnect PolygonConnect_30 [All] p0 off: scope1count=1 scope1_0_kind=Board scope1_0_value=Board scope2count=1 scope2_0_kind=Board scope2_0_value=Board commentlength=80 connectstyle=Direct reliefconductorwidth=0.254 reliefentries=4 polygonreliefangle="90 Angle" // Protel DXP Scope 2 Expression Was: IsNamedPolygon('SIGNAL_LAYER_2_GND_P082')
PolygonConnect PolygonConnect_29 [All] p0 off: scope1count=1 scope1_0_kind=Board scope1_0_value=Board scope2count=1 scope2_0_kind=Board scope2_0_value=Board commentlength=75 connectstyle=Direct reliefconductorwidth=0.254 reliefentries=4 polygonreliefangle="90 Angle" // Protel DXP Scope 2 Expression Was: IsNamedPolygon('TOP_LAYER_GND_P076')
PolygonConnect PolygonConnect_28 [All] p0 off: scope1count=1 scope1_0_kind=Board scope1_0_value=Board scope2count=1 scope2_0_kind=Board scope2_0_value=Board commentlength=75 connectstyle=Direct reliefconductorwidth=0.254 reliefentries=4 polygonreliefangle="90 Angle" // Protel DXP Scope 2 Expression Was: IsNamedPolygon('TOP_LAYER_GND_P087')
PolygonConnect PolygonConnect_27 [All] p0 off: scope1count=1 scope1_0_kind=Board scope1_0_value=Board scope2count=1 scope2_0_kind=Board scope2_0_value=Board commentlength=114 connectstyle=Direct reliefconductorwidth=0.254 reliefentries=4 polygonreliefangle="90 Angle" // Protel DXP Scope 2 Expression Was: IsNamedPolygon('TOP_LAYER_VM_P127') Or  IsNamedPolygon('TOP_LAYER_VM_P085')
PolygonConnect PolygonConnect_26 [All] p0 off: scope1count=1 scope1_0_kind=Board scope1_0_value=Board scope2count=1 scope2_0_kind=Board scope2_0_value=Board commentlength=75 connectstyle=Direct reliefconductorwidth=0.254 reliefentries=4 polygonreliefangle="90 Angle" // Protel DXP Scope 2 Expression Was: IsNamedPolygon('TOP_LAYER_GND_P117')
PolygonConnect PolygonConnect_25 [All] p0 off: scope1count=1 scope1_0_kind=Board scope1_0_value=Board scope2count=1 scope2_0_kind=Board scope2_0_value=Board commentlength=118 connectstyle=Direct reliefconductorwidth=0.254 reliefentries=4 polygonreliefangle="90 Angle" // Protel DXP Scope 2 Expression Was: IsNamedPolygon('TOP_LAYER_OUT1_P129') Or  IsNamedPolygon('TOP_LAYER_OUT2_P173')
PolygonConnect PolygonConnect_24 [All] p0 off: scope1count=1 scope1_0_kind=Board scope1_0_value=Board scope2count=1 scope2_0_kind=Board scope2_0_value=Board commentlength=82 connectstyle=Direct reliefconductorwidth=0.254 reliefentries=4 polygonreliefangle="90 Angle" // Protel DXP Scope 2 Expression Was: IsNamedPolygon('SIGNAL_LAYER_2_NONET_P113')
PolygonConnect PolygonConnect_23 [All] p0 off: scope1count=1 scope1_0_kind=Board scope1_0_value=Board scope2count=1 scope2_0_kind=Board scope2_0_value=Board commentlength=80 connectstyle=Direct reliefconductorwidth=0.254 reliefentries=4 polygonreliefangle="90 Angle" // Protel DXP Scope 2 Expression Was: IsNamedPolygon('BOTTOM_LAYER_NONET_P115')
PolygonConnect PolygonConnect_22 [All] p0 off: scope1count=1 scope1_0_kind=Board scope1_0_value=Board scope2count=1 scope2_0_kind=Board scope2_0_value=Board commentlength=82 connectstyle=Direct reliefconductorwidth=0.254 reliefentries=4 polygonreliefangle="90 Angle" // Protel DXP Scope 2 Expression Was: IsNamedPolygon('SIGNAL_LAYER_1_NONET_P111')
PolygonConnect PolygonConnect_21 [All] p0 off: scope1count=1 scope1_0_kind=Board scope1_0_value=Board scope2count=1 scope2_0_kind=Board scope2_0_value=Board commentlength=77 connectstyle=Direct reliefconductorwidth=0.254 reliefentries=4 polygonreliefangle="90 Angle" // Protel DXP Scope 2 Expression Was: IsNamedPolygon('TOP_LAYER_NONET_P083')
PolygonConnect PolygonConnect_20 [All] p0 off: scope1count=1 scope1_0_kind=Board scope1_0_value=Board scope2count=1 scope2_0_kind=Board scope2_0_value=Board commentlength=77 connectstyle=Direct reliefconductorwidth=0.254 reliefentries=4 polygonreliefangle="90 Angle" // Protel DXP Scope 2 Expression Was: IsNamedPolygon('TOP_LAYER_NONET_P105')
PolygonConnect PolygonConnect_19 [All] p0 off: scope1count=1 scope1_0_kind=Board scope1_0_value=Board scope2count=1 scope2_0_kind=Board scope2_0_value=Board commentlength=76 connectstyle=Direct reliefconductorwidth=0.254 reliefentries=4 polygonreliefangle="90 Angle" // Protel DXP Scope 2 Expression Was: IsNamedPolygon('TOP_LAYER_OUT2_P107')
PolygonConnect PolygonConnect_18 [All] p0 off: scope1count=1 scope1_0_kind=Board scope1_0_value=Board scope2count=1 scope2_0_kind=Board scope2_0_value=Board commentlength=77 connectstyle=Direct reliefconductorwidth=0.254 reliefentries=4 polygonreliefangle="90 Angle" // Protel DXP Scope 2 Expression Was: IsNamedPolygon('TOP_LAYER_NONET_P101')
PolygonConnect PolygonConnect_17 [All] p0 off: scope1count=1 scope1_0_kind=Board scope1_0_value=Board scope2count=1 scope2_0_kind=Board scope2_0_value=Board commentlength=76 connectstyle=Direct reliefconductorwidth=0.254 reliefentries=4 polygonreliefangle="90 Angle" // Protel DXP Scope 2 Expression Was: IsNamedPolygon('TOP_LAYER_OUT1_P103')
PolygonConnect PolygonConnect_16 [All] p0 off: scope1count=1 scope1_0_kind=Board scope1_0_value=Board scope2count=1 scope2_0_kind=Board scope2_0_value=Board commentlength=76 connectstyle=Direct reliefconductorwidth=0.254 reliefentries=4 polygonreliefangle="90 Angle" // Protel DXP Scope 2 Expression Was: IsNamedPolygon('TOP_LAYER_OUT1_P000')
PolygonConnect PolygonConnect_15 [All] p0 off: scope1count=1 scope1_0_kind=Board scope1_0_value=Board scope2count=1 scope2_0_kind=Board scope2_0_value=Board commentlength=77 connectstyle=Direct reliefconductorwidth=0.254 reliefentries=4 polygonreliefangle="90 Angle" // Protel DXP Scope 2 Expression Was: IsNamedPolygon('TOP_LAYER_NONET_P093')
PolygonConnect PolygonConnect_14 [All] p0 off: scope1count=1 scope1_0_kind=Board scope1_0_value=Board scope2count=1 scope2_0_kind=Board scope2_0_value=Board commentlength=76 connectstyle=Direct reliefconductorwidth=0.254 reliefentries=4 polygonreliefangle="90 Angle" // Protel DXP Scope 2 Expression Was: IsNamedPolygon('TOP_LAYER_OUT2_P099')
PolygonConnect PolygonConnect_13 [All] p0 off: scope1count=1 scope1_0_kind=Board scope1_0_value=Board scope2count=1 scope2_0_kind=Board scope2_0_value=Board commentlength=76 connectstyle=Direct reliefconductorwidth=0.254 reliefentries=4 polygonreliefangle="90 Angle" // Protel DXP Scope 2 Expression Was: IsNamedPolygon('TOP_LAYER_OUT1_P000')
PolygonConnect PolygonConnect_12 [All] p0 off: scope1count=1 scope1_0_kind=Board scope1_0_value=Board scope2count=1 scope2_0_kind=Board scope2_0_value=Board commentlength=933 connectstyle=Direct reliefconductorwidth=0.254 reliefentries=4 polygonreliefangle="90 Angle" // Protel DXP Scope 2 Expression Was: IsNamedPolygon('BOTTOM_LAYER_NONET_P079') Or  IsNamedPolygon('SIGNAL_LAYER_2_NONET_P078') Or  IsNamedPolygon('SIGNAL_LAYER_1_NONET_P077') Or  IsNamedPolygon('TOP_LAYER_NONET_P083') Or  IsNamedPolygon('BOTTOM_LAYER_NONET_P072') Or  IsNamedPolygon('SIGNAL_LAYER_2_NONET_P070') Or  IsNamedPolygon('SIGNAL_LAYER_1_NONET_P059') Or  IsNamedPolygon('TOP_LAYER_OUT2_P058') Or  IsNamedPolygon('BOTTOM_LAYER_NONET_P056') Or  IsNamedPolygon('SIGNAL_LAYER_2_NONET_P054') Or  IsNamedPolygon('SIGNAL_LAYER_1_NONET_P052') Or  IsNamedPolygon('TOP_LAYER_OUT1_P050') Or  IsNamedPolygon('BOTTOM_LAYER_VM_P044') Or  IsNamedPolygon('SIGNAL_LAYER_2_VM_P042') Or  IsNamedPolygon('SIGNAL_LAYER_1_VM_P040') Or  IsNamedPolygon('TOP_LAYER_VM_P038') Or  IsNamedPolygon('BOTTOM_LAYER_VM_P036') Or  IsNamedPolygon('SIGNAL_LAYER_2_VM_P018') Or  IsNamedPolygon('SIGNAL_LAYER_1_VM_P016') Or  IsNamedPolygon('TOP_LAYER_VM_P002')
PolygonConnect PolygonConnect_11 [All] p0 off: scope1count=1 scope1_0_kind=Board scope1_0_value=Board scope2count=1 scope2_0_kind=Board scope2_0_value=Board commentlength=120 connectstyle=Direct reliefconductorwidth=0.254 reliefentries=4 polygonreliefangle="90 Angle" // Protel DXP Scope 2 Expression Was: IsNamedPolygon('TOP_LAYER_NONET_P089') Or  IsNamedPolygon('TOP_LAYER_NONET_P090')
PolygonConnect PolygonConnect_10 [All] p0 off: scope1count=1 scope1_0_kind=Board scope1_0_value=Board scope2count=1 scope2_0_kind=Board scope2_0_value=Board commentlength=250 connectstyle=Direct reliefconductorwidth=0.254 reliefentries=4 polygonreliefangle="90 Angle" // Protel DXP Scope 2 Expression Was: IsNamedPolygon('BOTTOM_LAYER_EZFET_USB_SHIELD_P002') Or  IsNamedPolygon('TOP_LAYER_EZFET_USB_SHIELD_P201') Or  IsNamedPolygon('SIGNAL_LAYER_2_EZFET_VBUS_P018') Or  IsNamedPolygon('SIGNAL_LAYER_2_EZFET_VCC_P016')
PolygonConnect PolygonConnect_9 [All] p0 off: scope1count=1 scope1_0_kind=Board scope1_0_value=Board scope2count=1 scope2_0_kind=Board scope2_0_value=Board commentlength=154 connectstyle=Direct reliefconductorwidth=0.254 reliefentries=4 polygonreliefangle="90 Angle" // Protel DXP Scope 2 Expression Was: IsNamedPolygon('TOP_LAYER_VM_P123') Or  IsNamedPolygon('TOP_LAYER_VM_P123') Or  IsNamedPolygon('TOP_LAYER_VM_P123')
PolygonConnect PolygonConnect_8 [All] p0 off: scope1count=1 scope1_0_kind=Board scope1_0_value=Board scope2count=1 scope2_0_kind=Board scope2_0_value=Board commentlength=77 connectstyle=Direct reliefconductorwidth=0.254 reliefentries=4 polygonreliefangle="90 Angle" // Protel DXP Scope 2 Expression Was: IsNamedPolygon('TOP_LAYER_NONET_P072')
PolygonConnect PolygonConnect_7 [All] p0 off: scope1count=1 scope1_0_kind=Board scope1_0_value=Board scope2count=1 scope2_0_kind=Board scope2_0_value=Board commentlength=77 connectstyle=Direct reliefconductorwidth=0.254 reliefentries=4 polygonreliefangle="90 Angle" // Protel DXP Scope 2 Expression Was: IsNamedPolygon('TOP_LAYER_NONET_P072')
PolygonConnect PolygonConnect_6 [All] p0 off: scope1count=1 scope1_0_kind=Board scope1_0_value=Board scope2count=1 scope2_0_kind=Board scope2_0_value=Board commentlength=74 connectstyle=Direct reliefconductorwidth=0.254 reliefentries=4 polygonreliefangle="90 Angle" // Protel DXP Scope 2 Expression Was: IsNamedPolygon('TOP_LAYER_VM_P042')
PolygonConnect PolygonConnect_5 [All] p0 off: scope1count=1 scope1_0_kind=Board scope1_0_value=Board scope2count=1 scope2_0_kind=Board scope2_0_value=Board commentlength=74 connectstyle=Direct reliefconductorwidth=0.254 reliefentries=4 polygonreliefangle="90 Angle" // Protel DXP Scope 2 Expression Was: IsNamedPolygon('TOP_LAYER_VM_P044')
PolygonConnect PolygonConnect_4 [All] p0 off: scope1count=1 scope1_0_kind=Board scope1_0_value=Board scope2count=1 scope2_0_kind=Board scope2_0_value=Board commentlength=74 connectstyle=Direct reliefconductorwidth=0.254 reliefentries=4 polygonreliefangle="90 Angle" // Protel DXP Scope 2 Expression Was: IsNamedPolygon('TOP_LAYER_VM_P046')
PolygonConnect PolygonConnect_3 [All] p0 off: scope1count=1 scope1_0_kind=Board scope1_0_value=Board scope2count=1 scope2_0_kind=Board scope2_0_value=Board commentlength=159 connectstyle=Direct reliefconductorwidth=0.254 reliefentries=4 polygonreliefangle="90 Angle" // Protel DXP Scope 2 Expression Was: IsNamedPolygon('TOP_LAYER_GND_P036') Or  IsNamedPolygon('TOP_LAYER_OUT2_P040') Or  IsNamedPolygon('TOP_LAYER_OUT1_P038')
PolygonConnect PolygonConnect_2 [All] p0 off: scope1count=1 scope1_0_kind=Net scope1_0_value=EZFET_VBUS scope2count=1 scope2_0_kind=Board scope2_0_value=Board commentlength=82 connectstyle=Direct reliefconductorwidth=0.254 reliefentries=4 polygonreliefangle="90 Angle" // Protel DXP Scope 2 Expression Was: IsNamedPolygon('TOP_LAYER_EZFET_VBUS_P008')
PolygonConnect PolygonConnect_1 [All] p0 off: scope1count=1 scope1_0_kind=NetClass scope1_0_value=Power-Net scope2count=1 scope2_0_kind=Board scope2_0_value=Board commentlength=88 connectstyle=Direct reliefconductorwidth=0.254 reliefentries=4 polygonreliefangle="90 Angle" // Protel DXP Scope 2 Expression Was: IsNamedPolygon('TOP_LAYER_EZFET_USB_SHIELD_P201')
PolygonConnect [All] p0: scope1count=1 scope1_0_kind=Board scope1_0_value=Board scope2count=1 scope2_0_kind=Board scope2_0_value=Board commentlength=0 connectstyle=Relief reliefconductorwidth=0.254 reliefentries=4 polygonreliefangle="90 Angle"
PolygonConnect PolygonConnect_87 [All vs IsNamedPolygon('TOP_LAYER_VM_P125')] p1: connectstyle=Direct reliefconductorwidth=0.254 reliefentries=4 polygonreliefangle="90 Angle" airgapwidth=0.254
PolygonConnect PolygonConnect_86 [All vs IsNamedPolygon('TOP_LAYER_NONET_P-001')] p2: connectstyle=Direct reliefconductorwidth=0.254 reliefentries=4 polygonreliefangle="90 Angle" airgapwidth=0.254
PolygonConnect PolygonConnect_85 [All vs IsNamedPolygon('BOTTOM_LAYER_OUT2_P211')] p3: connectstyle=Direct reliefconductorwidth=0.254 reliefentries=4 polygonreliefangle="90 Angle" airgapwidth=0.254
PolygonConnect PolygonConnect_84 [All vs IsNamedPolygon('BOTTOM_LAYER_OUT1_P205')] p4: connectstyle=Direct reliefconductorwidth=0.254 reliefentries=4 polygonreliefangle="90 Angle" airgapwidth=0.254
PolygonConnect PolygonConnect_83 [All vs IsNamedPolygon('BOTTOM_LAYER_OUT1_P205')] p5: connectstyle=Direct reliefconductorwidth=0.254 reliefentries=4 polygonreliefangle="90 Angle" airgapwidth=0.254
PolygonConnect PolygonConnect_82 [All vs IsNamedPolygon('BOTTOM_LAYER_GND_P204')] p6: connectstyle=Direct reliefconductorwidth=0.254 reliefentries=4 polygonreliefangle="90 Angle" airgapwidth=0.254
PolygonConnect PolygonConnect_81 [All vs IsNamedPolygon('TOP_LAYER_GND_P237')] p7: connectstyle=Direct reliefconductorwidth=0.254 reliefentries=4 polygonreliefangle="90 Angle" airgapwidth=0.254
PolygonConnect PolygonConnect_80 [All vs IsNamedPolygon('TOP_LAYER_GND_P086')] p8: connectstyle=Direct reliefconductorwidth=0.254 reliefentries=4 polygonreliefangle="90 Angle" airgapwidth=0.254
PolygonConnect PolygonConnect_79 [All vs IsNamedPolygon('TOP_LAYER_VM_P229')] p9: connectstyle=Direct reliefconductorwidth=0.254 reliefentries=4 polygonreliefangle="90 Angle" airgapwidth=0.254
PolygonConnect PolygonConnect_78 [All vs IsNamedPolygon('TOP_LAYER_GND_P086')] p10: connectstyle=Direct reliefconductorwidth=0.254 reliefentries=4 polygonreliefangle="90 Angle" airgapwidth=0.254
PolygonConnect PolygonConnect_77 [All vs IsNamedPolygon('TOP_LAYER_OUT1_P221')] p11: connectstyle=Direct reliefconductorwidth=0.254 reliefentries=4 polygonreliefangle="90 Angle" airgapwidth=0.254
PolygonConnect PolygonConnect_76 [All vs IsNamedPolygon('TOP_LAYER_OUT2_P173')] p12: connectstyle=Direct reliefconductorwidth=0.254 reliefentries=4 polygonreliefangle="90 Angle" airgapwidth=0.254
PolygonConnect PolygonConnect_75 [All vs IsNamedPolygon('TOP_LAYER_OUT2_P173')] p13: connectstyle=Direct reliefconductorwidth=0.254 reliefentries=4 polygonreliefangle="90 Angle" airgapwidth=0.254
PolygonConnect PolygonConnect_74 [All vs IsNamedPolygon('TOP_LAYER_OUT2_P173')] p14: connectstyle=Direct reliefconductorwidth=0.254 reliefentries=4 polygonreliefangle="90 Angle" airgapwidth=0.254
PolygonConnect PolygonConnect_73 [All vs IsNamedPolygon('TOP_LAYER_OUT1_P221')] p15: connectstyle=Direct reliefconductorwidth=0.254 reliefentries=4 polygonreliefangle="90 Angle" airgapwidth=0.254
PolygonConnect PolygonConnect_72 [All vs IsNamedPolygon('TOP_LAYER_GND_P121')] p16: connectstyle=Direct reliefconductorwidth=0.254 reliefentries=4 polygonreliefangle="90 Angle" airgapwidth=0.254
PolygonConnect PolygonConnect_71 [All vs IsNamedPolygon('TOP_LAYER_OUT2_P173') Or  IsNamedPolygon('TOP_LAYER_OUT1_P129')] p17: connectstyle=Direct reliefconductorwidth=0.254 reliefentries=4 polygonreliefangle="90 Angle" airgapwidth=0.254
PolygonConnect PolygonConnect_70 [All vs IsNamedPolygon('TOP_LAYER_OUT2_P173')] p18: connectstyle=Direct reliefconductorwidth=0.254 reliefentries=4 polygonreliefangle="90 Angle" airgapwidth=0.254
